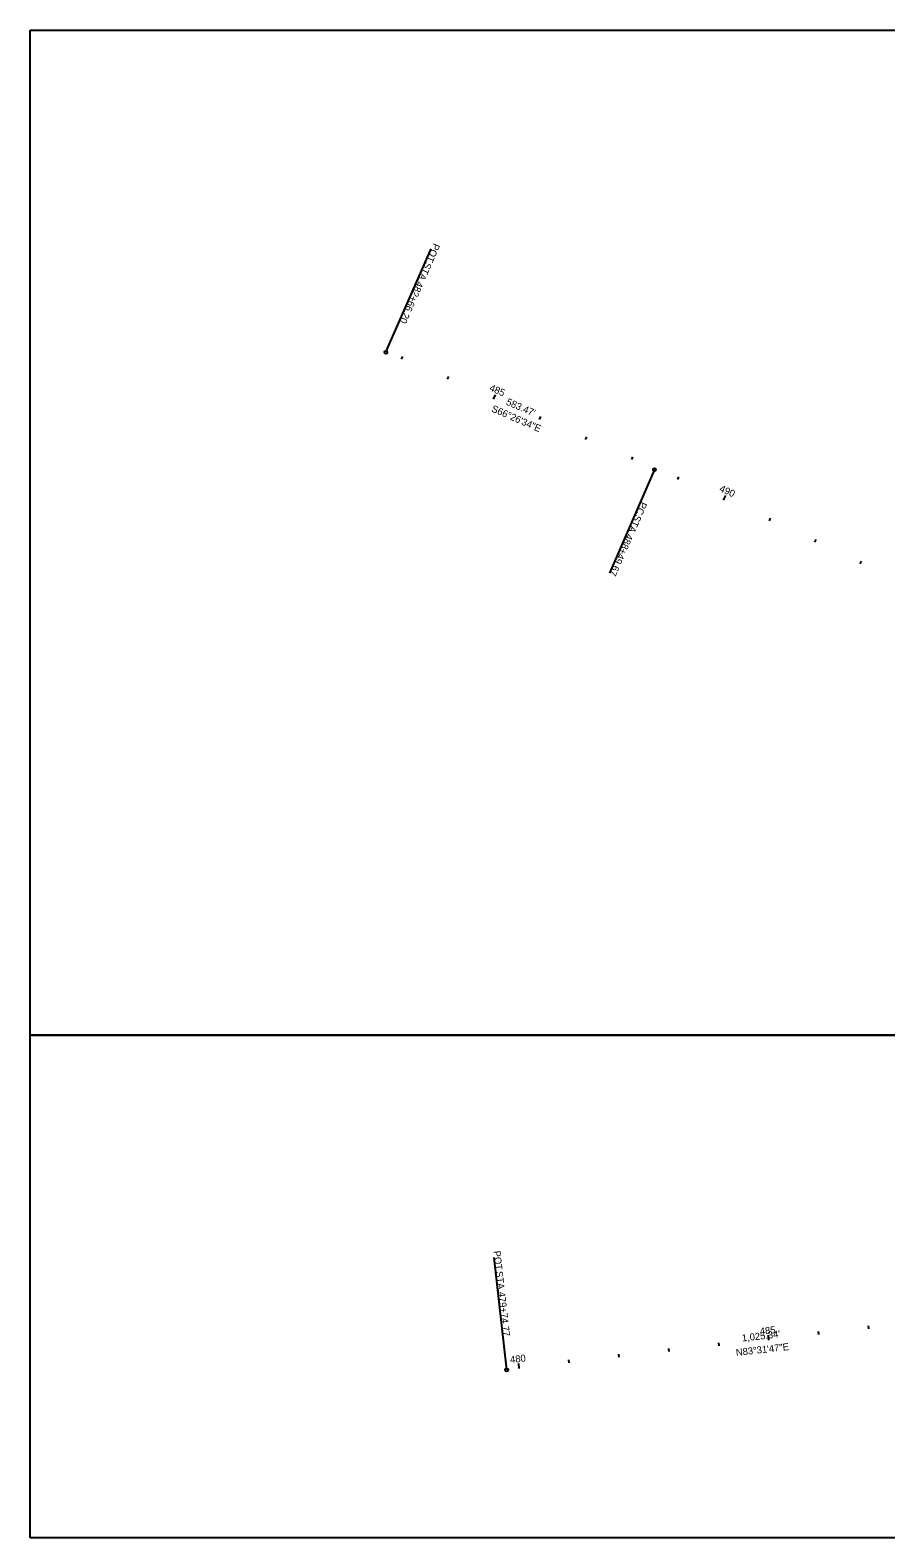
# Model space of a CAD drawing. Extents: x 1597353 to 1604853, y 283653 to 289007.
# Drawn here: x 1597353 to 1599057, y 286007 to 289007 of the extents above; entities that cross this region are included whole.
import ezdxf

# ---------------------------------------------------------------- set-up
doc = ezdxf.new("R2010")
doc.units = 0
for name, color, linetype in [('_CIVIL_CONSTRUCTION', 7, 'Continuous'), ('GE_X_Alignment_100_Cardinal_Points', 7, 'Continuous'), ('GE_X_Alignment_100_Curve_Data', 7, 'Continuous'), ('GE_X_Alignment_100_Distances', 7, 'Continuous'), ('GE_X_Alignment_100_Stations', 7, 'Continuous')]:
    doc.layers.add(name, color=color, linetype=linetype)

msp = doc.modelspace()

# ---------------------------------------------------------------- linework, layer by layer
at = {"layer": '_CIVIL_CONSTRUCTION'}
msp.add_line((1599853.4, 286006.5), (1597353.4, 286006.5), dxfattribs=at)
msp.add_lwpolyline([(1597353.4, 289006.5), (1599853.4, 289006.5), (1599853.4, 287006.5), (1597353.4, 287006.5)], close=True, dxfattribs=at)
msp.add_lwpolyline([(1597353.4, 286006.5), (1597353.4, 287006.5), (1599853.4, 287006.5), (1599853.4, 286006.5)], dxfattribs=at)
at = {"layer": 'GE_X_Alignment_100_Curve_Data'}
for p, q in [((1598061.5, 288365.5), (1598151.4, 288571.7)), ((1598596.3, 288132.3), (1598506.4, 287926)), ((1598302, 286340.6), (1598276.7, 286564.2))]:
    msp.add_line(p, q, dxfattribs=at)
for centre in [(1598061.5, 288365.5), (1598596.3, 288132.3), (1598302, 286340.6)]:
    msp.add_circle(centre, 3, dxfattribs=at)
at = {"layer": 'GE_X_Alignment_100_Stations'}
for p, q in [((1598092.5, 288352), (1598094.9, 288357.5)), ((1598184.1, 288312), (1598186.5, 288317.5)), ((1598275.8, 288272), (1598279.8, 288281.2)), ((1598367.5, 288232.1), (1598369.9, 288237.6)), ((1598459.1, 288192.1), (1598461.5, 288197.6)), ((1598550.8, 288152.1), (1598553.2, 288157.6)), ((1598642.4, 288112.1), (1598644.8, 288117.6)), ((1598733.8, 288071.4), (1598737.9, 288080.5)), ((1598824.8, 288029.9), (1598827.3, 288035.4)), ((1598915.4, 287987.7), (1598918, 287993.1)), ((1599005.7, 287944.8), (1599008.3, 287950.2)), ((1598923.3, 286411.1), (1598922.6, 286417.1)), ((1599022.6, 286422.4), (1599022, 286428.3)), ((1598625.2, 286377.3), (1598624.5, 286383.3)), ((1598724.6, 286388.6), (1598723.9, 286394.5)), ((1598823.9, 286399.8), (1598822.8, 286409.8)), ((1598327.1, 286343.5), (1598326, 286353.4)), ((1598426.5, 286354.8), (1598425.8, 286360.7)), ((1598525.8, 286366), (1598525.1, 286372))]:
    msp.add_line(p, q, dxfattribs=at)

# ---------------------------------------------------------------- texts
at = {"layer": 'GE_X_Alignment_100_Cardinal_Points'}
for s, rotation, p in [('S66°26\'34"E', 336.4429, (1598270.2, 288248.3)), ('N83°31\'47"E', 6.4702, (1598758.9, 286368.3))]:
    msp.add_text(s, height=14, rotation=rotation, dxfattribs=at).set_placement(p)
at = {"layer": 'GE_X_Alignment_100_Curve_Data'}
for s, rotation, p in [('POT', 246.4429, (1598156.8, 288583.6)), (' STA. ', 246.4429, (1598142.5, 288550.9)), ('482+66.20', 246.4429, (1598123.9, 288508.2)), ('PC', 246.4429, (1598569.1, 288069.5)), (' STA. ', 246.4429, (1598560, 288048.4)), ('488+49.67', 246.4429, (1598541.3, 288005.7)), ('POT', 276.4702, (1598275.4, 286577)), (' STA. ', 276.4702, (1598279.4, 286541.6)), ('479+74.77', 276.4702, (1598284.7, 286495.3))]:
    msp.add_text(s, height=14, rotation=rotation, dxfattribs=at).set_placement(p)
at = {"layer": 'GE_X_Alignment_100_Distances'}
for s, rotation, p in [("583.47'", 336.4429, (1598299.5, 288261.9)), ("1,025.34'", 6.4702, (1598770.9, 286397))]:
    msp.add_text(s, height=14, rotation=rotation, dxfattribs=at).set_placement(p)
at = {"layer": 'GE_X_Alignment_100_Stations'}
for s, rotation, p in [('485', 336.4429, (1598266.1, 288289.9)), ('490', 335.7414, (1598724, 288089.5)), ('485', 6.4702, (1598806.6, 286410.4)), ('480', 6.4702, (1598309.5, 286354.1))]:
    msp.add_text(s, height=14, rotation=rotation, dxfattribs=at).set_placement(p)

doc.saveas('drawing.dxf')
